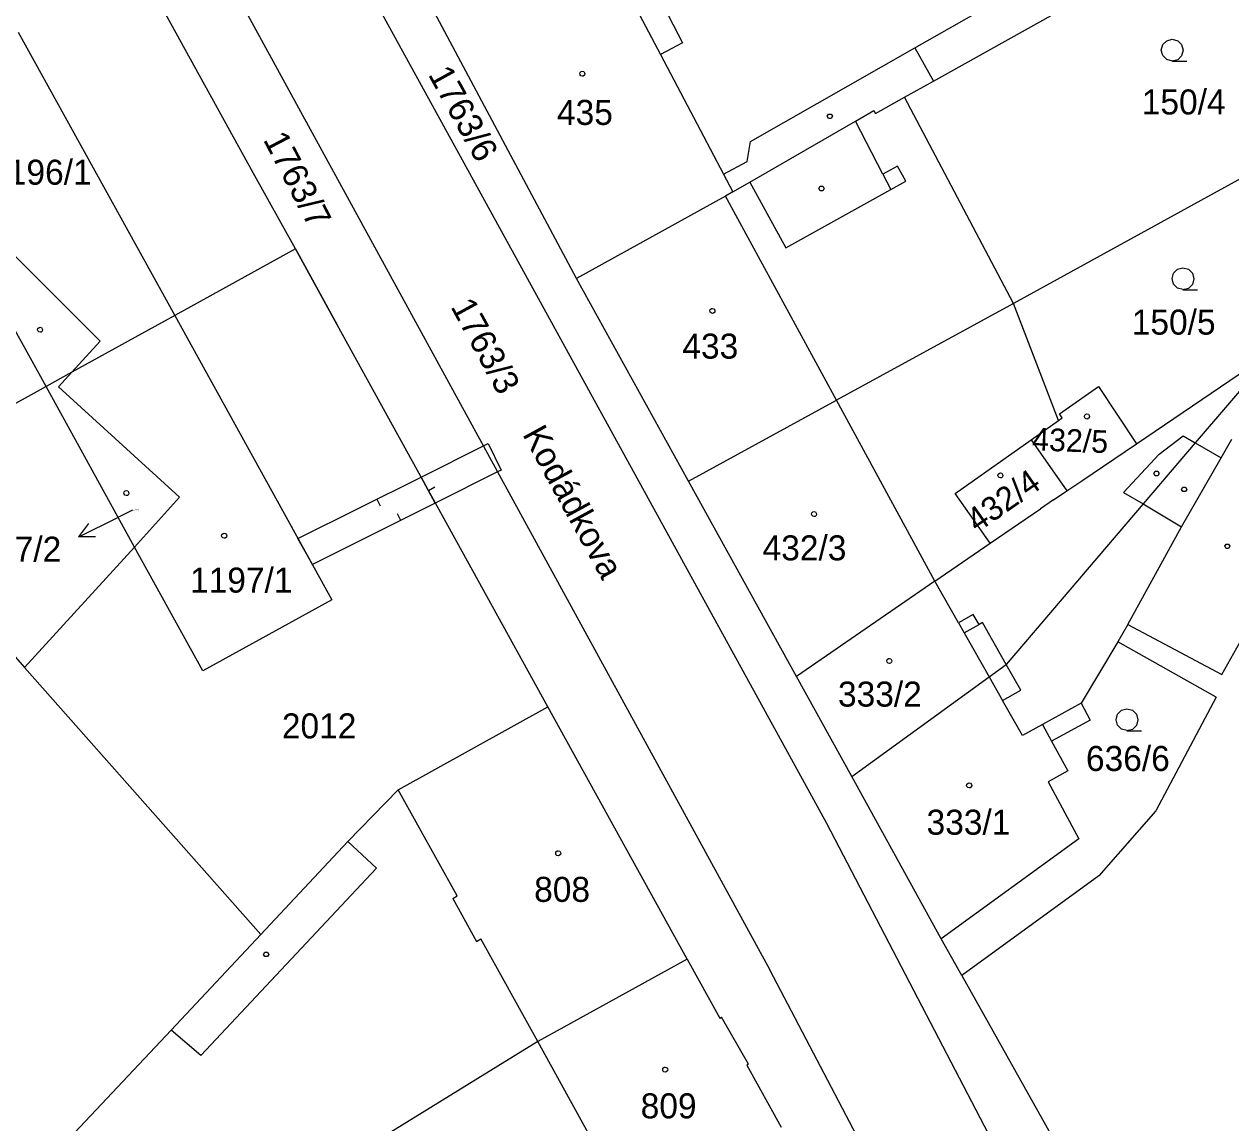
# Model space of a CAD drawing. Extents: x -777309 to -774195, y -1144706 to -1143600.
# Drawn here: x -774533.6 to -774451.7, y -1144313.4 to -1144238.8 of the extents above; entities that cross this region are included whole.
import ezdxf

# ---------------------------------------------------------------- set-up
doc = ezdxf.new("R2010")
doc.units = 0
for name, color, linetype in [('1', 7, 'Continuous'), ('11', 7, 'Continuous'), ('12', 7, 'Continuous'), ('13', 7, 'Continuous'), ('2', 7, 'Continuous'), ('3', 7, 'Continuous'), ('4', 7, 'Continuous'), ('5', 7, 'Continuous'), ('7', 7, 'Continuous')]:
    doc.layers.add(name, color=color, linetype=linetype)

msp = doc.modelspace()

# ---------------------------------------------------------------- linework, layer by layer
at = {"layer": '1'}
for p, q in [((-774539.29, -1144200.03), (-774483.01, -1144303.01)), ((-774471.92, -1144242.66), (-774447.92, -1144229.21)), ((-774518.08, -1144248.89), (-774528.56, -1144229.85)), ((-774479.16, -1144293.08), (-774510.56, -1144235.84)), ((-774496.13, -1144256.06), (-774506.84, -1144236.01)), ((-774437.34, -1144241.73), (-774466.49, -1144257.77)), ((-774473.88, -1144243.76), (-774471.92, -1144242.66)), ((-774475.85, -1144244.87), (-774473.88, -1144243.76)), ((-774466.49, -1144257.77), (-774473.88, -1144243.76)), ((-774477.21, -1144245.39), (-774475.96, -1144244.67)), ((-774475.96, -1144244.67), (-774475.85, -1144244.87)), ((-774484.37, -1144249.52), (-774477.21, -1144245.39)), ((-774528.46, -1144260.33), (-774540.47, -1144248.34)), ((-774515.22, -1144254.06), (-774518.08, -1144248.89)), ((-774485.53, -1144250.19), (-774484.37, -1144249.52)), ((-774486.03, -1144250.47), (-774496.13, -1144256.06)), ((-774485.53, -1144250.19), (-774486.03, -1144250.47)), ((-774515.22, -1144254.06), (-774523.4, -1144258.58)), ((-774515.22, -1144254.06), (-774512.39, -1144259.21)), ((-774488.54, -1144269.82), (-774496.13, -1144256.06)), ((-774466.49, -1144257.77), (-774478.5, -1144264.33)), ((-774463.42, -1144265.71), (-774466.49, -1144257.77)), ((-774523.4, -1144258.58), (-774530.39, -1144262.44)), ((-774523.4, -1144258.58), (-774512.74, -1144277.88)), ((-774498.09, -1144285.16), (-774512.39, -1144259.21)), ((-774530.39, -1144262.44), (-774528.46, -1144260.33)), ((-774458.14, -1144267.29), (-774448.8, -1144260.96)), ((-774448.8, -1144260.96), (-774454.15, -1144267.23)), ((-774530.39, -1144262.44), (-774532.14, -1144263.41)), ((-774531.29, -1144263.43), (-774530.39, -1144262.44)), ((-774532.14, -1144263.41), (-774544.37, -1144270.17)), ((-774523.09, -1144270.91), (-774531.29, -1144263.43)), ((-774463.37, -1144265.26), (-774460.72, -1144263.4)), ((-774460.72, -1144263.4), (-774458.14, -1144267.29)), ((-774488.54, -1144269.82), (-774478.5, -1144264.33)), ((-774463.42, -1144265.71), (-774463.17, -1144265.54)), ((-774463.17, -1144265.54), (-774463.37, -1144265.26)), ((-774465.28, -1144267.03), (-774463.42, -1144265.71)), ((-774470.43, -1144270.66), (-774465.28, -1144267.03)), ((-774465.28, -1144267.03), (-774462.86, -1144270.49)), ((-774454.15, -1144267.23), (-774457.68, -1144271.38)), ((-774452.38, -1144268.24), (-774451.67, -1144266.98)), ((-774461.84, -1144269.8), (-774458.14, -1144267.29)), ((-774455.07, -1144272.93), (-774452.38, -1144268.24)), ((-774544.37, -1144270.17), (-774533.61, -1144282.48)), ((-774481.2, -1144283.09), (-774488.54, -1144269.82)), ((-774463.76, -1144271.09), (-774462.86, -1144270.49)), ((-774462.86, -1144270.49), (-774461.84, -1144269.8)), ((-774526.13, -1144274.31), (-774523.09, -1144270.91)), ((-774468.07, -1144274.05), (-774470.43, -1144270.66)), ((-774463.76, -1144271.09), (-774464.65, -1144271.7)), ((-774468.07, -1144274.05), (-774464.65, -1144271.7)), ((-774457.68, -1144271.38), (-774466.97, -1144282.28)), ((-774458.73, -1144279.57), (-774455.07, -1144272.93)), ((-774526.13, -1144274.31), (-774533.61, -1144282.48)), ((-774521.49, -1144282.71), (-774526.13, -1144274.31)), ((-774471.82, -1144276.62), (-774468.07, -1144274.05)), ((-774471.82, -1144276.62), (-774481.2, -1144283.09)), ((-774512.74, -1144277.88), (-774521.49, -1144282.71)), ((-774452.35, -1144282.97), (-774449.42, -1144277.74)), ((-774458.73, -1144279.57), (-774459.39, -1144280.73)), ((-774458.73, -1144279.57), (-774452.35, -1144282.97)), ((-774459.39, -1144280.73), (-774461.88, -1144284.91)), ((-774452.72, -1144284.49), (-774459.39, -1144280.73)), ((-774533.61, -1144282.48), (-774517.56, -1144300.62)), ((-774468.14, -1144283.12), (-774466.97, -1144282.28)), ((-774477.46, -1144289.88), (-774481.2, -1144283.09)), ((-774477.46, -1144289.88), (-774468.14, -1144283.12)), ((-774508.23, -1144290.78), (-774498.09, -1144285.16)), ((-774488.62, -1144302.3), (-774498.09, -1144285.16)), ((-774461.88, -1144284.91), (-774461.27, -1144286.05)), ((-774452.72, -1144284.49), (-774456.83, -1144292.22)), ((-774461.27, -1144286.05), (-774463.9, -1144287.49)), ((-774463.9, -1144287.49), (-774462.8, -1144289.5)), ((-774471.39, -1144300.9), (-774477.46, -1144289.88)), ((-774462.8, -1144289.5), (-774464.13, -1144290.25)), ((-774511.66, -1144294.29), (-774508.23, -1144290.78)), ((-774464.13, -1144290.25), (-774462.04, -1144294.11)), ((-774456.83, -1144292.22), (-774460.68, -1144296.62)), ((-774462.94, -1144324.16), (-774479.16, -1144293.08)), ((-774462.04, -1144294.11), (-774471.39, -1144300.9)), ((-774517.56, -1144300.62), (-774511.66, -1144294.29)), ((-774460.68, -1144296.62), (-774469.99, -1144303.4)), ((-774523.64, -1144307.11), (-774517.56, -1144300.62)), ((-774469.99, -1144303.4), (-774471.39, -1144300.9)), ((-774488.62, -1144302.3), (-774498.77, -1144307.88)), ((-774488.62, -1144302.3), (-774486.41, -1144306.3)), ((-774471.92, -1144324.17), (-774483.01, -1144303.01)), ((-774469.99, -1144303.4), (-774460.03, -1144321.17)), ((-774486.41, -1144306.3), (-774486.29, -1144306.23)), ((-774484.47, -1144309.43), (-774486.29, -1144306.23)), ((-774530.94, -1144314.86), (-774523.64, -1144307.11)), ((-774498.77, -1144307.88), (-774525.9, -1144324.6)), ((-774484.47, -1144309.43), (-774484.59, -1144309.48)), ((-774484.59, -1144309.48), (-774482.26, -1144313.69))]:
    msp.add_line(p, q, dxfattribs=at)
at = {"layer": '11'}
msp.add_lwpolyline([(-774508.23, -1144290.78), (-774498.09, -1144285.16), (-774512.39, -1144259.21), (-774515.22, -1144254.06), (-774523.4, -1144258.58), (-774512.74, -1144277.88), (-774521.49, -1144282.71), (-774526.13, -1144274.31), (-774533.61, -1144282.48), (-774517.56, -1144300.62), (-774511.66, -1144294.29)], close=True, dxfattribs=at)
at = {"layer": '12'}
for p, q in [((-774496.13, -1144256.06), (-774506.84, -1144236.01)), ((-774492.06, -1144237.79), (-774490.44, -1144240.86)), ((-774534.02, -1144239.34), (-774523.4, -1144258.58)), ((-774490.44, -1144240.86), (-774486.17, -1144248.98)), ((-774532.14, -1144263.41), (-774540.47, -1144248.34)), ((-774486.17, -1144248.98), (-774485.53, -1144250.19)), ((-774486.03, -1144250.47), (-774496.13, -1144256.06)), ((-774486.03, -1144250.47), (-774496.13, -1144256.06)), ((-774485.53, -1144250.19), (-774486.03, -1144250.47)), ((-774478.5, -1144264.33), (-774486.03, -1144250.47)), ((-774488.54, -1144269.82), (-774496.13, -1144256.06)), ((-774523.4, -1144258.58), (-774530.39, -1144262.44)), ((-774523.4, -1144258.58), (-774530.39, -1144262.44)), ((-774523.4, -1144258.58), (-774512.74, -1144277.88)), ((-774530.39, -1144262.44), (-774532.14, -1144263.41)), ((-774530.39, -1144262.44), (-774532.14, -1144263.41)), ((-774526.13, -1144274.31), (-774532.14, -1144263.41)), ((-774463.37, -1144265.26), (-774460.72, -1144263.4)), ((-774460.72, -1144263.4), (-774458.14, -1144267.29)), ((-774488.54, -1144269.82), (-774478.5, -1144264.33)), ((-774488.54, -1144269.82), (-774478.5, -1144264.33)), ((-774473.81, -1144272.96), (-774478.5, -1144264.33)), ((-774463.42, -1144265.71), (-774463.17, -1144265.54)), ((-774463.17, -1144265.54), (-774463.37, -1144265.26)), ((-774465.28, -1144267.03), (-774463.42, -1144265.71)), ((-774470.43, -1144270.66), (-774465.28, -1144267.03)), ((-774465.28, -1144267.03), (-774462.86, -1144270.49)), ((-774465.28, -1144267.03), (-774462.86, -1144270.49)), ((-774461.84, -1144269.8), (-774458.14, -1144267.29)), ((-774481.2, -1144283.09), (-774488.54, -1144269.82)), ((-774463.76, -1144271.09), (-774462.86, -1144270.49)), ((-774462.86, -1144270.49), (-774461.84, -1144269.8)), ((-774468.07, -1144274.05), (-774470.43, -1144270.66)), ((-774463.76, -1144271.09), (-774464.65, -1144271.7)), ((-774468.07, -1144274.05), (-774464.65, -1144271.7)), ((-774471.82, -1144276.62), (-774473.81, -1144272.96)), ((-774521.49, -1144282.71), (-774526.13, -1144274.31)), ((-774471.82, -1144276.62), (-774481.2, -1144283.09)), ((-774471.82, -1144276.62), (-774481.2, -1144283.09)), ((-774470.22, -1144279.44), (-774471.82, -1144276.62)), ((-774512.74, -1144277.88), (-774521.49, -1144282.71)), ((-774470.22, -1144279.44), (-774469.83, -1144280.14)), ((-774469.83, -1144280.14), (-774468.14, -1144283.12)), ((-774477.46, -1144289.88), (-774481.2, -1144283.09)), ((-774477.46, -1144289.88), (-774468.14, -1144283.12)), ((-774477.46, -1144289.88), (-774468.14, -1144283.12)), ((-774468.14, -1144283.12), (-774467.23, -1144284.72)), ((-774508.23, -1144290.78), (-774498.09, -1144285.16)), ((-774488.62, -1144302.3), (-774498.09, -1144285.16)), ((-774465.88, -1144287.11), (-774467.23, -1144284.72)), ((-774464.52, -1144286.36), (-774465.88, -1144287.11)), ((-774464.52, -1144286.36), (-774463.9, -1144287.49)), ((-774463.9, -1144287.49), (-774462.8, -1144289.5)), ((-774471.39, -1144300.9), (-774477.46, -1144289.88)), ((-774462.8, -1144289.5), (-774464.13, -1144290.25)), ((-774504.24, -1144298), (-774508.23, -1144290.78)), ((-774464.13, -1144290.25), (-774462.04, -1144294.11)), ((-774462.04, -1144294.11), (-774471.39, -1144300.9)), ((-774504.53, -1144298.16), (-774504.24, -1144298)), ((-774504.53, -1144298.16), (-774502.92, -1144301.09)), ((-774502.92, -1144301.09), (-774502.62, -1144300.92)), ((-774498.77, -1144307.88), (-774502.62, -1144300.92)), ((-774488.62, -1144302.3), (-774498.77, -1144307.88)), ((-774488.62, -1144302.3), (-774498.77, -1144307.88)), ((-774488.62, -1144302.3), (-774486.41, -1144306.3)), ((-774486.41, -1144306.3), (-774486.29, -1144306.23)), ((-774484.47, -1144309.43), (-774486.29, -1144306.23)), ((-774492.47, -1144319.27), (-774498.77, -1144307.88)), ((-774484.47, -1144309.43), (-774484.59, -1144309.48)), ((-774484.59, -1144309.48), (-774482.26, -1144313.69))]:
    msp.add_line(p, q, dxfattribs=at)
at = {"layer": '13'}
for p, q in [((-774506.19, -1144270.462), (-774505.752, -1144270.221)), ((-774509.693, -1144271.05), (-774509.47, -1144271.497)), ((-774508.068, -1144272.494), (-774508.291, -1144272.047))]:
    msp.add_line(p, q, dxfattribs=at)
for points in [[(-774502.14, -1144267.28), (-774501.24, -1144269.08), (-774501.49, -1144269.2), (-774505.72, -1144271.32), (-774506.69, -1144269.55), (-774502.45, -1144267.44)], [(-774514.06, -1144275.49), (-774515.04, -1144273.72), (-774506.69, -1144269.55), (-774505.72, -1144271.32)]]:
    msp.add_lwpolyline(points, close=True, dxfattribs=at)
at = {"layer": '3'}
for points in [[(-774455.7, -1144241.3), (-774456.08, -1144241.2), (-774456.35, -1144240.93), (-774456.45, -1144240.56), (-774456.35, -1144240.19), (-774456.08, -1144239.92), (-774455.71, -1144239.82), (-774455.34, -1144239.92), (-774455.07, -1144240.19), (-774454.97, -1144240.57), (-774455.07, -1144240.95), (-774455.34, -1144241.22), (-774455.72, -1144241.32), (-774454.72, -1144241.32)], [(-774454.97, -1144256.82), (-774455.35, -1144256.72), (-774455.62, -1144256.45), (-774455.72, -1144256.08), (-774455.62, -1144255.71), (-774455.35, -1144255.44), (-774454.98, -1144255.34), (-774454.61, -1144255.44), (-774454.34, -1144255.71), (-774454.24, -1144256.09), (-774454.34, -1144256.47), (-774454.61, -1144256.74), (-774454.99, -1144256.84), (-774453.99, -1144256.84)], [(-774458.77, -1144286.77), (-774459.15, -1144286.67), (-774459.42, -1144286.4), (-774459.52, -1144286.03), (-774459.42, -1144285.66), (-774459.15, -1144285.39), (-774458.78, -1144285.29), (-774458.41, -1144285.39), (-774458.14, -1144285.66), (-774458.04, -1144286.04), (-774458.14, -1144286.42), (-774458.41, -1144286.69), (-774458.79, -1144286.79), (-774457.79, -1144286.79)]]:
    msp.add_lwpolyline(points, dxfattribs=at)
at = {"layer": '4'}
for p, q in [((-774473.18, -1144240.41), (-774451.53, -1144228.05)), ((-774490.53, -1144236.98), (-774488.94, -1144240.07)), ((-774492.06, -1144237.79), (-774490.44, -1144240.86)), ((-774534.02, -1144239.34), (-774523.4, -1144258.58)), ((-774488.94, -1144240.07), (-774490.44, -1144240.86)), ((-774490.44, -1144240.86), (-774486.17, -1144248.98)), ((-774484.33, -1144246.77), (-774473.18, -1144240.41)), ((-774473.18, -1144240.41), (-774471.92, -1144242.66)), ((-774475.34, -1144248.99), (-774477.21, -1144245.39)), ((-774484.55, -1144248.13), (-774484.33, -1144246.77)), ((-774532.14, -1144263.41), (-774540.47, -1144248.34)), ((-774486.17, -1144248.98), (-774484.55, -1144248.13)), ((-774486.17, -1144248.98), (-774485.53, -1144250.19)), ((-774474.35, -1144248.44), (-774475.34, -1144248.99)), ((-774475.34, -1144248.99), (-774474.81, -1144250.03)), ((-774473.78, -1144249.46), (-774474.35, -1144248.44)), ((-774484.37, -1144249.52), (-774481.93, -1144253.98)), ((-774481.93, -1144253.98), (-774474.81, -1144250.03)), ((-774474.81, -1144250.03), (-774473.78, -1144249.46)), ((-774478.5, -1144264.33), (-774486.03, -1144250.47)), ((-774526.13, -1144274.31), (-774532.14, -1144263.41)), ((-774473.81, -1144272.96), (-774478.5, -1144264.33)), ((-774456.59, -1144268), (-774454.96, -1144266.76)), ((-774454.96, -1144266.76), (-774454.15, -1144267.23)), ((-774454.15, -1144267.23), (-774452.38, -1144268.24)), ((-774459.02, -1144270.59), (-774456.59, -1144268)), ((-774459.02, -1144270.59), (-774457.68, -1144271.38)), ((-774457.68, -1144271.38), (-774455.07, -1144272.93)), ((-774471.82, -1144276.62), (-774473.81, -1144272.96)), ((-774470.22, -1144279.44), (-774471.82, -1144276.62)), ((-774469.21, -1144278.88), (-774470.22, -1144279.44)), ((-774470.22, -1144279.44), (-774469.83, -1144280.14)), ((-774468.82, -1144279.57), (-774469.21, -1144278.88)), ((-774468.58, -1144279.43), (-774468.82, -1144279.57)), ((-774466.97, -1144282.28), (-774468.58, -1144279.43)), ((-774469.83, -1144280.14), (-774468.82, -1144279.57)), ((-774469.83, -1144280.14), (-774468.14, -1144283.12)), ((-774465.98, -1144284.02), (-774466.97, -1144282.28)), ((-774468.14, -1144283.12), (-774467.23, -1144284.72)), ((-774467.23, -1144284.72), (-774465.98, -1144284.02)), ((-774465.88, -1144287.11), (-774467.23, -1144284.72)), ((-774461.88, -1144284.91), (-774464.52, -1144286.36)), ((-774464.52, -1144286.36), (-774465.88, -1144287.11)), ((-774464.52, -1144286.36), (-774463.9, -1144287.49)), ((-774504.24, -1144298), (-774508.23, -1144290.78)), ((-774511.66, -1144294.29), (-774509.72, -1144296.11)), ((-774509.72, -1144296.11), (-774521.63, -1144308.83)), ((-774504.53, -1144298.16), (-774504.24, -1144298)), ((-774504.53, -1144298.16), (-774502.92, -1144301.09)), ((-774502.92, -1144301.09), (-774502.62, -1144300.92)), ((-774498.77, -1144307.88), (-774502.62, -1144300.92)), ((-774521.63, -1144308.83), (-774523.64, -1144307.11)), ((-774492.47, -1144319.27), (-774498.77, -1144307.88))]:
    msp.add_line(p, q, dxfattribs=at)
at = {"layer": '5'}
for points in [[(-774495.75, -1144242), (-774495.65, -1144242.02), (-774495.6, -1144242.11), (-774495.58, -1144242.17), (-774495.6, -1144242.26), (-774495.68, -1144242.33), (-774495.75, -1144242.34), (-774495.84, -1144242.31), (-774495.9, -1144242.25), (-774495.92, -1144242.17), (-774495.9, -1144242.08), (-774495.82, -1144242.01)], [(-774478.86, -1144244.9), (-774478.77, -1144245.05), (-774478.86, -1144245.2), (-774479.04, -1144245.2), (-774479.13, -1144245.05), (-774479.04, -1144244.9)], [(-774479.43, -1144249.81), (-774479.34, -1144249.96), (-774479.43, -1144250.11), (-774479.61, -1144250.11), (-774479.7, -1144249.96), (-774479.61, -1144249.81)], [(-774486.91, -1144258.1), (-774486.81, -1144258.12), (-774486.76, -1144258.21), (-774486.74, -1144258.27), (-774486.76, -1144258.36), (-774486.84, -1144258.43), (-774486.91, -1144258.44), (-774487, -1144258.41), (-774487.06, -1144258.35), (-774487.08, -1144258.27), (-774487.06, -1144258.18), (-774486.98, -1144258.11)], [(-774532.54, -1144259.38), (-774532.44, -1144259.4), (-774532.39, -1144259.49), (-774532.37, -1144259.55), (-774532.39, -1144259.64), (-774532.47, -1144259.71), (-774532.54, -1144259.72), (-774532.63, -1144259.69), (-774532.69, -1144259.63), (-774532.71, -1144259.55), (-774532.69, -1144259.46), (-774532.61, -1144259.39)], [(-774461.5, -1144265.27), (-774461.4, -1144265.29), (-774461.35, -1144265.38), (-774461.33, -1144265.44), (-774461.35, -1144265.53), (-774461.43, -1144265.6), (-774461.5, -1144265.61), (-774461.59, -1144265.58), (-774461.65, -1144265.52), (-774461.67, -1144265.44), (-774461.65, -1144265.35), (-774461.57, -1144265.28)], [(-774467.37, -1144269.27), (-774467.27, -1144269.29), (-774467.22, -1144269.38), (-774467.2, -1144269.44), (-774467.22, -1144269.53), (-774467.3, -1144269.6), (-774467.37, -1144269.61), (-774467.46, -1144269.58), (-774467.52, -1144269.52), (-774467.54, -1144269.44), (-774467.52, -1144269.35), (-774467.44, -1144269.28)], [(-774456.69, -1144269.16), (-774456.6, -1144269.31), (-774456.69, -1144269.46), (-774456.87, -1144269.46), (-774456.96, -1144269.31), (-774456.87, -1144269.16)], [(-774526.69, -1144270.47), (-774526.59, -1144270.49), (-774526.54, -1144270.58), (-774526.52, -1144270.64), (-774526.54, -1144270.73), (-774526.62, -1144270.8), (-774526.69, -1144270.81), (-774526.78, -1144270.78), (-774526.84, -1144270.72), (-774526.86, -1144270.64), (-774526.84, -1144270.55), (-774526.76, -1144270.48)], [(-774454.81, -1144270.24), (-774454.72, -1144270.39), (-774454.81, -1144270.54), (-774454.99, -1144270.54), (-774455.08, -1144270.39), (-774454.99, -1144270.24)], [(-774480.02, -1144271.9), (-774479.92, -1144271.92), (-774479.87, -1144272.01), (-774479.85, -1144272.07), (-774479.87, -1144272.16), (-774479.95, -1144272.23), (-774480.02, -1144272.24), (-774480.11, -1144272.21), (-774480.17, -1144272.15), (-774480.19, -1144272.07), (-774480.17, -1144271.98), (-774480.09, -1144271.91)], [(-774520.05, -1144273.37), (-774519.95, -1144273.39), (-774519.9, -1144273.48), (-774519.88, -1144273.54), (-774519.9, -1144273.63), (-774519.98, -1144273.7), (-774520.05, -1144273.71), (-774520.14, -1144273.68), (-774520.2, -1144273.62), (-774520.22, -1144273.54), (-774520.2, -1144273.45), (-774520.12, -1144273.38)], [(-774451.88, -1144274.1), (-774451.79, -1144274.25), (-774451.88, -1144274.4), (-774452.06, -1144274.4), (-774452.15, -1144274.25), (-774452.06, -1144274.1)], [(-774474.9, -1144281.87), (-774474.8, -1144281.89), (-774474.75, -1144281.98), (-774474.73, -1144282.04), (-774474.75, -1144282.13), (-774474.83, -1144282.2), (-774474.9, -1144282.21), (-774474.99, -1144282.18), (-774475.05, -1144282.12), (-774475.07, -1144282.04), (-774475.05, -1144281.95), (-774474.97, -1144281.88)], [(-774469.49, -1144290.32), (-774469.39, -1144290.34), (-774469.34, -1144290.43), (-774469.32, -1144290.49), (-774469.34, -1144290.58), (-774469.42, -1144290.65), (-774469.49, -1144290.66), (-774469.58, -1144290.63), (-774469.64, -1144290.57), (-774469.66, -1144290.49), (-774469.64, -1144290.4), (-774469.56, -1144290.33)], [(-774497.38, -1144294.93), (-774497.28, -1144294.95), (-774497.23, -1144295.04), (-774497.21, -1144295.1), (-774497.23, -1144295.19), (-774497.31, -1144295.26), (-774497.38, -1144295.27), (-774497.47, -1144295.24), (-774497.53, -1144295.18), (-774497.55, -1144295.1), (-774497.53, -1144295.01), (-774497.45, -1144294.94)], [(-774517.1, -1144301.82), (-774517.01, -1144301.97), (-774517.1, -1144302.12), (-774517.28, -1144302.12), (-774517.37, -1144301.97), (-774517.28, -1144301.82)], [(-774490.12, -1144309.62), (-774490.02, -1144309.64), (-774489.97, -1144309.73), (-774489.95, -1144309.79), (-774489.97, -1144309.88), (-774490.05, -1144309.95), (-774490.12, -1144309.96), (-774490.21, -1144309.93), (-774490.27, -1144309.87), (-774490.29, -1144309.79), (-774490.27, -1144309.7), (-774490.19, -1144309.63)]]:
    msp.add_lwpolyline(points, close=True, dxfattribs=at)
at = {"layer": '7'}
for p in [(-774526.26, -1144271.81), (-774529.902, -1144273.604)]:
    msp.add_line(p, (-774527.21, -1144272.28), dxfattribs=at)
msp.add_lwpolyline([(-774528.784, -1144273.612), (-774529.902, -1144273.604), (-774529.225, -1144272.714)], dxfattribs=at)

# ---------------------------------------------------------------- texts
at = {"layer": '2'}
for s, height, rotation, p in [('1763/6', 1.7, 298.96938, (-774506.24, -1144242.214)), ('1763/7', 1.7, 297.53698, (-774517.428, -1144246.638)), ('1763/3', 1.7, 298.51101, (-774504.713, -1144257.975)), ('432/5', 1.54, 357.86944, (-774465.236, -1144267.737)), ('432/4', 1.62, 35.06502, (-774468.943, -1144273.368))]:
    msp.add_text(s, height=height, rotation=rotation, dxfattribs=at).set_placement(p)
for s, height, p in [('150/4', 1.7, (-774457.777, -1144244.93)), ('435', 1.7, (-774497.463, -1144245.64)), ('1196/1', 1.7, (-774535.997, -1144249.7)), ('150/5', 1.7, (-774458.456, -1144259.88)), ('433', 1.7, (-774488.953, -1144261.51)), ('1197/2', 0.1, (-774526.237, -1144271.81)), ('432/3', 1.7, (-774483.511, -1144275.21)), ('1197/1', 1.7, (-774522.367, -1144277.4)), ('333/2', 1.7, (-774478.393, -1144285.14)), ('2012', 1.7, (-774516.133, -1144287.3)), ('636/6', 1.7, (-774461.563, -1144289.51)), ('333/1', 1.7, (-774472.383, -1144293.84)), ('808', 1.7, (-774499.013, -1144298.4)), ('809', 1.7, (-774491.783, -1144313.1))]:
    msp.add_text(s, height=height, dxfattribs=at).set_placement(p)
at = {"layer": '7'}
msp.add_text('Kodádkova', height=1.7, rotation=298.6829, dxfattribs=at).set_placement((-774499.839, -1144266.643))
msp.add_text('1197/2', height=1.7, dxfattribs=at).set_placement((-774538.058, -1144275.3))

doc.saveas('drawing.dxf')
